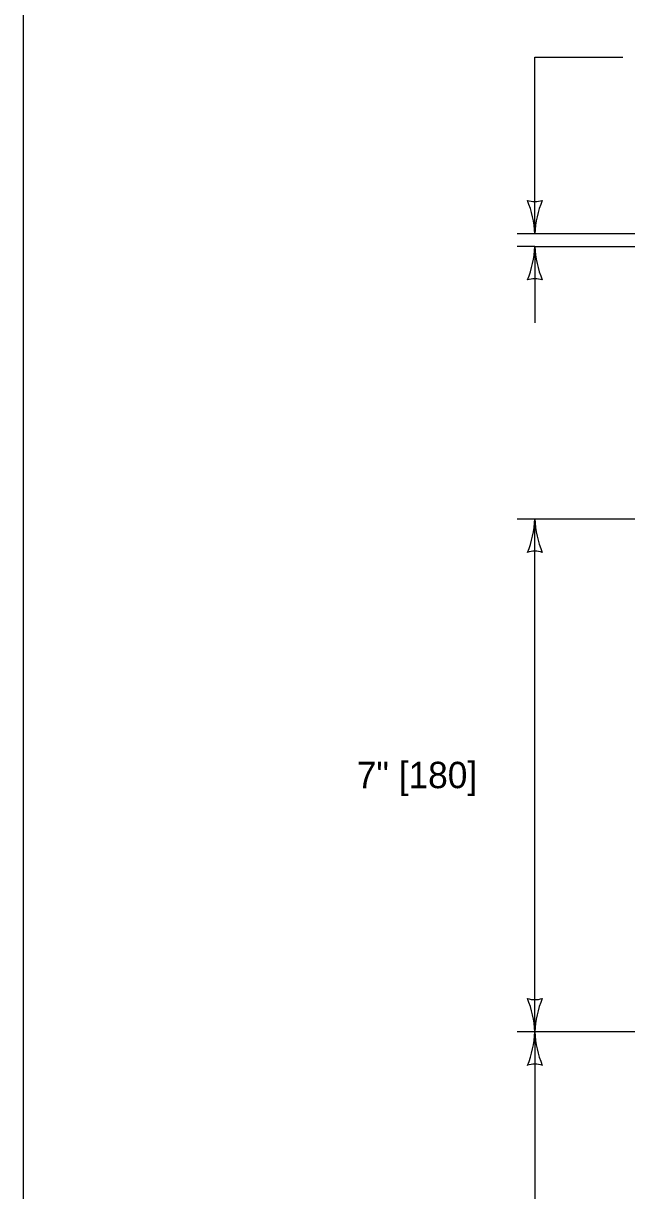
# Model space of a CAD drawing. Extents: x 49991.4 to 50021, y 49987.6 to 50011.4.
# Drawn here: x 49999.384 to 50000.755, y 49994.619 to 49997.274 of the extents above; entities that cross this region are included whole.
import ezdxf

# ---------------------------------------------------------------- set-up
doc = ezdxf.new("R2010")
doc.units = 0
for name, color, linetype in [('Level 1', 7, 'Continuous'), ('Level 2', 7, 'Continuous'), ('Level 3', 7, 'Continuous')]:
    doc.layers.add(name, color=color, linetype=linetype)

msp = doc.modelspace()

# ---------------------------------------------------------------- linework, layer by layer
at = {"layer": 'Level 1'}
msp.add_lwpolyline([(49999.3835, 49998.9992), (50016.7501, 49998.9992), (50016.7501, 49987.7988), (49999.3835, 49987.7988)], close=True, dxfattribs=at)
at = {"layer": 'Level 3'}
for p, q in [((50000.5464, 49996.7952), (50000.5464, 49997.1968)), ((50000.5464, 49997.1968), (50000.7464, 49997.1968)), ((50000.5464, 49996.7952), (50000.5064, 49996.7952)), ((50001.0779, 49996.7952), (50000.5464, 49996.7952)), ((50000.5464, 49996.7665), (50000.5064, 49996.7665)), ((50000.5464, 49996.7665), (50000.5464, 49996.593)), ((50000.5464, 49996.7665), (50002.5321, 49996.7665)), ((50000.5064, 49996.1466), (50002.9723, 49996.1466)), ((50000.5464, 49994.982), (50000.5464, 49996.1466)), ((50002.0526, 49994.98), (50000.5064, 49994.98)), ((50000.5464, 49994.98), (50000.5464, 49990.6029))]:
    msp.add_line(p, q, dxfattribs=at)
for centre, radius, start, end in [((50000.5464, 49996.9234), 0.0548, 252.1388, 287.8612), ((50000.3137, 49996.7837), 0.233, 2.8273, 22.0772), ((50000.7686, 49996.786), 0.2223, 157.456, 177.6395), ((50000.3243, 49996.7756), 0.2223, 337.456, 357.6395), ((50000.3243, 49996.7756), 0.2223, 337.456, 357.6395), ((50000.7791, 49996.778), 0.233, 182.8273, 202.0772), ((50000.7791, 49996.778), 0.233, 182.8273, 202.0772), ((50000.5464, 49996.6382), 0.0548, 72.1388, 107.8612), ((50000.5464, 49996.6382), 0.0548, 72.1388, 107.8612), ((50000.3243, 49996.1557), 0.2223, 337.456, 357.6395), ((50000.7791, 49996.1581), 0.233, 182.8273, 202.0772), ((50000.5464, 49996.0184), 0.0548, 72.1388, 107.8612), ((50000.5464, 49995.1082), 0.0548, 252.1388, 287.8612), ((50000.3137, 49994.9685), 0.233, 2.8273, 22.0772), ((50000.7686, 49994.9708), 0.2223, 157.456, 177.6395), ((50000.3243, 49994.9891), 0.2223, 337.456, 357.6395), ((50000.7791, 49994.9915), 0.233, 182.8273, 202.0772), ((50000.5464, 49994.8518), 0.0548, 72.1388, 107.8612)]:
    msp.add_arc(centre, radius, start, end, dxfattribs=at)

# ---------------------------------------------------------------- texts
at = {"layer": 'Level 2'}
msp.add_text('7" [180]', height=0.06, dxfattribs=at).set_placement((50000.1415, 49995.5343))

doc.saveas('drawing.dxf')
